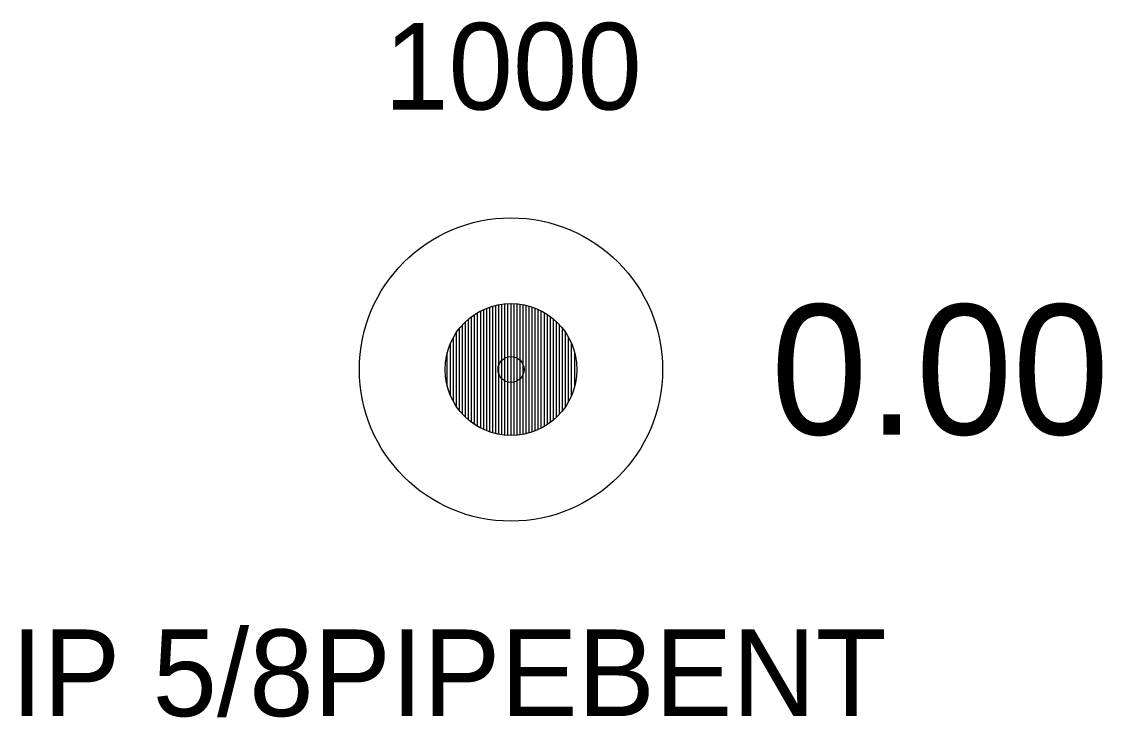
# Model space of a CAD drawing. Extents: x 2529517 to 2532038, y 935000 to 936944.
# Drawn here: x 2529593.86 to 2529606.33, y 935546.37 to 935554.4 of the extents above; entities that cross this region are included whole.
import ezdxf

# ---------------------------------------------------------------- set-up
doc = ezdxf.new("R2010")
doc.units = 0
for name, color, linetype in [('RD_EX_DV_Prop_txCode', 7, 'Continuous'), ('RD_EX_DV_PropPin', 7, 'Continuous'), ('RD_EX_TX_DV_Prop_ELEV', 7, 'Continuous'), ('RD_SMD_Locator', 7, 'Continuous')]:
    doc.layers.add(name, color=color, linetype=linetype)

msp = doc.modelspace()

# ---------------------------------------------------------------- linework, layer by layer
at = {"layer": 'RD_EX_DV_PropPin'}
for p, q in [((2529599.332, 935549.646), (2529599.332, 935551.128)), ((2529599.367, 935549.639), (2529599.367, 935551.135)), ((2529599.402, 935549.633), (2529599.402, 935551.141)), ((2529599.437, 935549.629), (2529599.437, 935551.145)), ((2529599.472, 935549.627), (2529599.472, 935551.147)), ((2529599.507, 935549.626), (2529599.507, 935551.148)), ((2529599.542, 935549.627), (2529599.542, 935551.147)), ((2529599.577, 935549.629), (2529599.577, 935551.145)), ((2529599.612, 935549.633), (2529599.612, 935551.141)), ((2529599.647, 935549.639), (2529599.647, 935551.135)), ((2529599.682, 935549.646), (2529599.682, 935551.128)), ((2529599.087, 935549.752), (2529599.087, 935551.021)), ((2529599.122, 935549.731), (2529599.122, 935551.043)), ((2529599.157, 935549.711), (2529599.157, 935551.063)), ((2529599.192, 935549.694), (2529599.192, 935551.08)), ((2529599.227, 935549.679), (2529599.227, 935551.094)), ((2529599.262, 935549.666), (2529599.262, 935551.107)), ((2529599.297, 935549.655), (2529599.297, 935551.118)), ((2529599.717, 935549.655), (2529599.717, 935551.118)), ((2529599.752, 935549.666), (2529599.752, 935551.107)), ((2529599.787, 935549.679), (2529599.787, 935551.094)), ((2529599.822, 935549.694), (2529599.822, 935551.08)), ((2529599.857, 935549.711), (2529599.857, 935551.063)), ((2529599.892, 935549.731), (2529599.892, 935551.043)), ((2529599.927, 935549.752), (2529599.927, 935551.021)), ((2529598.947, 935549.872), (2529598.947, 935550.902)), ((2529598.982, 935549.836), (2529598.982, 935550.938)), ((2529599.017, 935549.805), (2529599.017, 935550.969)), ((2529599.052, 935549.777), (2529599.052, 935550.997)), ((2529599.962, 935549.777), (2529599.962, 935550.997)), ((2529599.997, 935549.805), (2529599.997, 935550.969)), ((2529600.032, 935549.836), (2529600.032, 935550.938)), ((2529600.067, 935549.872), (2529600.067, 935550.902)), ((2529598.842, 935550.017), (2529598.842, 935550.756)), ((2529598.877, 935549.96), (2529598.877, 935550.813)), ((2529598.912, 935549.913), (2529598.912, 935550.861)), ((2529600.102, 935549.913), (2529600.102, 935550.861)), ((2529600.137, 935549.96), (2529600.137, 935550.813)), ((2529600.172, 935550.017), (2529600.172, 935550.756)), ((2529598.807, 935550.089), (2529598.807, 935550.685)), ((2529600.207, 935550.089), (2529600.207, 935550.685)), ((2529598.772, 935550.191), (2529598.772, 935550.583)), ((2529600.242, 935550.191), (2529600.242, 935550.583))]:
    msp.add_line(p, q, dxfattribs=at)
for radius in [1.75, 0.761]:
    msp.add_circle((2529599.507, 935550.387), radius, dxfattribs=at)
at = {"layer": 'RD_SMD_Locator'}
msp.add_circle((2529599.507, 935550.387), 0.15, dxfattribs=at)

# ---------------------------------------------------------------- texts
at = {"layer": 'RD_EX_DV_Prop_txCode'}
for s, p in [('1000', (2529598.042, 935553.387)), ('IP 5/8PIPEBENT', (2529593.735, 935546.387))]:
    msp.add_text(s, height=1, dxfattribs=at).set_placement(p)
at = {"layer": 'RD_EX_TX_DV_Prop_ELEV'}
msp.add_text('0.00', height=1.5, dxfattribs=at).set_placement((2529602.507, 935549.637))

doc.saveas('drawing.dxf')
